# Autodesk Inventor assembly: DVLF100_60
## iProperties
Created: 2010-03
Part Number: DVLF100_60
Document SubType Name: Assembly
Designer: TB
Mass: 3438.6 g
Surface Area: 3688.72 cm^2
Volume: 3438.6 cm^3
Density: 1 g/cm^3
Description: KM DVLF 100/60 - 100 mm
Slaglengde: 100.000 mm
Author: TB
